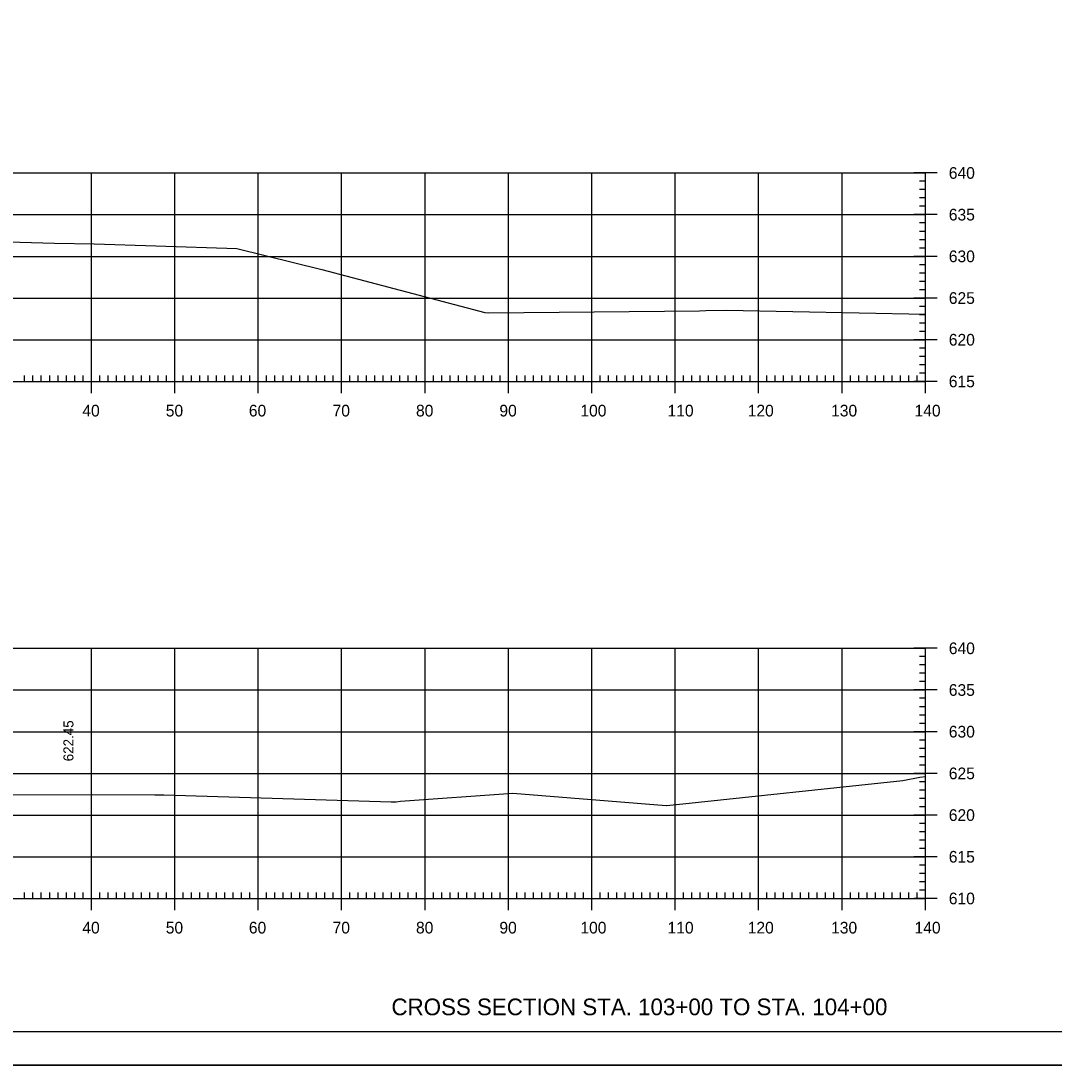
# Model space of a CAD drawing. Extents: x 1381471 to 1382703, y 370300 to 371487.
# Drawn here: x 1382168.2 to 1382292, y 370847.1 to 370972.4 of the extents above; entities that cross this region are included whole.
import ezdxf

# ---------------------------------------------------------------- set-up
doc = ezdxf.new("R2010")
doc.units = 0
doc.layers.add('Level 45', color=7, linetype='Continuous')

msp = doc.modelspace()

# ---------------------------------------------------------------- linework, layer by layer
at = {"layer": 'Level 45'}
for p, q in [((1381996.61, 370954.12), (1382276.61, 370954.12)), ((1382176.61, 370929.12), (1382176.61, 370954.12)), ((1382186.61, 370929.12), (1382186.61, 370954.12)), ((1382196.61, 370929.12), (1382196.61, 370954.12)), ((1382206.61, 370929.12), (1382206.61, 370954.12)), ((1382216.61, 370929.12), (1382216.61, 370954.12)), ((1382226.61, 370929.12), (1382226.61, 370954.12)), ((1382236.61, 370929.12), (1382236.61, 370954.12)), ((1382246.61, 370929.12), (1382246.61, 370954.12)), ((1382256.61, 370929.12), (1382256.61, 370954.12)), ((1382266.61, 370929.12), (1382266.61, 370954.12)), ((1382278.01, 370954.12), (1382275.21, 370954.12)), ((1382276.61, 370929.12), (1382276.61, 370954.12)), ((1382276.61, 370929.12), (1382276.61, 370954.12)), ((1382276.61, 370953.12), (1382275.91, 370953.12)), ((1382276.61, 370952.12), (1382275.91, 370952.12)), ((1382276.61, 370951.12), (1382275.91, 370951.12)), ((1382276.61, 370950.12), (1382275.91, 370950.12)), ((1381996.61, 370949.12), (1382276.61, 370949.12)), ((1382278.01, 370949.12), (1382275.21, 370949.12)), ((1382276.61, 370948.12), (1382275.91, 370948.12)), ((1382276.61, 370947.12), (1382275.91, 370947.12)), ((1382276.61, 370946.12), (1382275.91, 370946.12)), ((1382276.61, 370945.12), (1382275.91, 370945.12)), ((1381996.61, 370944.12), (1382276.61, 370944.12)), ((1382278.01, 370944.12), (1382275.21, 370944.12)), ((1382276.61, 370943.12), (1382275.91, 370943.12)), ((1382276.61, 370942.12), (1382275.91, 370942.12)), ((1382276.61, 370941.12), (1382275.91, 370941.12)), ((1382276.61, 370940.12), (1382275.91, 370940.12)), ((1381996.61, 370939.12), (1382276.61, 370939.12)), ((1382278.01, 370939.12), (1382275.21, 370939.12)), ((1382276.61, 370938.12), (1382275.91, 370938.12)), ((1382276.61, 370937.12), (1382275.91, 370937.12)), ((1382276.61, 370936.12), (1382275.91, 370936.12)), ((1382276.61, 370935.12), (1382275.91, 370935.12)), ((1381996.61, 370934.12), (1382276.61, 370934.12)), ((1382278.01, 370934.12), (1382275.21, 370934.12)), ((1382276.61, 370933.12), (1382275.91, 370933.12)), ((1382276.61, 370932.12), (1382275.91, 370932.12)), ((1382276.61, 370931.12), (1382275.91, 370931.12)), ((1382168.61, 370929.12), (1382168.61, 370929.82)), ((1382169.61, 370929.12), (1382169.61, 370929.82)), ((1382170.61, 370929.12), (1382170.61, 370929.82)), ((1382171.61, 370929.12), (1382171.61, 370929.82)), ((1382172.61, 370929.12), (1382172.61, 370929.82)), ((1382173.61, 370929.12), (1382173.61, 370929.82)), ((1382174.61, 370929.12), (1382174.61, 370929.82)), ((1382175.61, 370929.12), (1382175.61, 370929.82)), ((1382176.61, 370927.72), (1382176.61, 370930.52)), ((1382177.61, 370929.12), (1382177.61, 370929.82)), ((1382178.61, 370929.12), (1382178.61, 370929.82)), ((1382179.61, 370929.12), (1382179.61, 370929.82)), ((1382180.61, 370929.12), (1382180.61, 370929.82)), ((1382181.61, 370929.12), (1382181.61, 370929.82)), ((1382182.61, 370929.12), (1382182.61, 370929.82)), ((1382183.61, 370929.12), (1382183.61, 370929.82)), ((1382184.61, 370929.12), (1382184.61, 370929.82)), ((1382185.61, 370929.12), (1382185.61, 370929.82)), ((1382186.61, 370927.72), (1382186.61, 370930.52)), ((1382187.61, 370929.12), (1382187.61, 370929.82)), ((1382188.61, 370929.12), (1382188.61, 370929.82)), ((1382189.61, 370929.12), (1382189.61, 370929.82)), ((1382190.61, 370929.12), (1382190.61, 370929.82)), ((1382191.61, 370929.12), (1382191.61, 370929.82)), ((1382192.61, 370929.12), (1382192.61, 370929.82)), ((1382193.61, 370929.12), (1382193.61, 370929.82)), ((1382194.61, 370929.12), (1382194.61, 370929.82)), ((1382195.61, 370929.12), (1382195.61, 370929.82)), ((1382196.61, 370927.72), (1382196.61, 370930.52)), ((1382197.61, 370929.12), (1382197.61, 370929.82)), ((1382198.61, 370929.12), (1382198.61, 370929.82)), ((1382199.61, 370929.12), (1382199.61, 370929.82)), ((1382200.61, 370929.12), (1382200.61, 370929.82)), ((1382201.61, 370929.12), (1382201.61, 370929.82)), ((1382202.61, 370929.12), (1382202.61, 370929.82)), ((1382203.61, 370929.12), (1382203.61, 370929.82)), ((1382204.61, 370929.12), (1382204.61, 370929.82)), ((1382205.61, 370929.12), (1382205.61, 370929.82)), ((1382206.61, 370927.72), (1382206.61, 370930.52)), ((1382207.61, 370929.12), (1382207.61, 370929.82)), ((1382208.61, 370929.12), (1382208.61, 370929.82)), ((1382209.61, 370929.12), (1382209.61, 370929.82)), ((1382210.61, 370929.12), (1382210.61, 370929.82)), ((1382211.61, 370929.12), (1382211.61, 370929.82)), ((1382212.61, 370929.12), (1382212.61, 370929.82)), ((1382213.61, 370929.12), (1382213.61, 370929.82)), ((1382214.61, 370929.12), (1382214.61, 370929.82)), ((1382215.61, 370929.12), (1382215.61, 370929.82)), ((1382216.61, 370927.72), (1382216.61, 370930.52)), ((1382217.61, 370929.12), (1382217.61, 370929.82)), ((1382218.61, 370929.12), (1382218.61, 370929.82)), ((1382219.61, 370929.12), (1382219.61, 370929.82)), ((1382220.61, 370929.12), (1382220.61, 370929.82)), ((1382221.61, 370929.12), (1382221.61, 370929.82)), ((1382222.61, 370929.12), (1382222.61, 370929.82)), ((1382223.61, 370929.12), (1382223.61, 370929.82)), ((1382224.61, 370929.12), (1382224.61, 370929.82)), ((1382225.61, 370929.12), (1382225.61, 370929.82)), ((1382226.61, 370927.72), (1382226.61, 370930.52)), ((1382227.61, 370929.12), (1382227.61, 370929.82)), ((1382228.61, 370929.12), (1382228.61, 370929.82)), ((1382229.61, 370929.12), (1382229.61, 370929.82)), ((1382230.61, 370929.12), (1382230.61, 370929.82)), ((1382231.61, 370929.12), (1382231.61, 370929.82)), ((1382232.61, 370929.12), (1382232.61, 370929.82)), ((1382233.61, 370929.12), (1382233.61, 370929.82)), ((1382234.61, 370929.12), (1382234.61, 370929.82)), ((1382235.61, 370929.12), (1382235.61, 370929.82)), ((1382236.61, 370927.72), (1382236.61, 370930.52)), ((1382237.61, 370929.12), (1382237.61, 370929.82)), ((1382238.61, 370929.12), (1382238.61, 370929.82)), ((1382239.61, 370929.12), (1382239.61, 370929.82)), ((1382240.61, 370929.12), (1382240.61, 370929.82)), ((1382241.61, 370929.12), (1382241.61, 370929.82)), ((1382242.61, 370929.12), (1382242.61, 370929.82)), ((1382243.61, 370929.12), (1382243.61, 370929.82)), ((1382244.61, 370929.12), (1382244.61, 370929.82)), ((1382245.61, 370929.12), (1382245.61, 370929.82)), ((1382246.61, 370927.72), (1382246.61, 370930.52)), ((1382247.61, 370929.12), (1382247.61, 370929.82)), ((1382248.61, 370929.12), (1382248.61, 370929.82)), ((1382249.61, 370929.12), (1382249.61, 370929.82)), ((1382250.61, 370929.12), (1382250.61, 370929.82)), ((1382251.61, 370929.12), (1382251.61, 370929.82)), ((1382252.61, 370929.12), (1382252.61, 370929.82)), ((1382253.61, 370929.12), (1382253.61, 370929.82)), ((1382254.61, 370929.12), (1382254.61, 370929.82)), ((1382255.61, 370929.12), (1382255.61, 370929.82)), ((1382256.61, 370927.72), (1382256.61, 370930.52)), ((1382257.61, 370929.12), (1382257.61, 370929.82)), ((1382258.61, 370929.12), (1382258.61, 370929.82)), ((1382259.61, 370929.12), (1382259.61, 370929.82)), ((1382260.61, 370929.12), (1382260.61, 370929.82)), ((1382261.61, 370929.12), (1382261.61, 370929.82)), ((1382262.61, 370929.12), (1382262.61, 370929.82)), ((1382263.61, 370929.12), (1382263.61, 370929.82)), ((1382264.61, 370929.12), (1382264.61, 370929.82)), ((1382265.61, 370929.12), (1382265.61, 370929.82)), ((1382266.61, 370927.72), (1382266.61, 370930.52)), ((1382267.61, 370929.12), (1382267.61, 370929.82)), ((1382268.61, 370929.12), (1382268.61, 370929.82)), ((1382269.61, 370929.12), (1382269.61, 370929.82)), ((1382270.61, 370929.12), (1382270.61, 370929.82)), ((1382271.61, 370929.12), (1382271.61, 370929.82)), ((1382272.61, 370929.12), (1382272.61, 370929.82)), ((1382273.61, 370929.12), (1382273.61, 370929.82)), ((1382274.61, 370929.12), (1382274.61, 370929.82)), ((1382275.61, 370929.12), (1382275.61, 370929.82)), ((1382276.61, 370930.12), (1382275.91, 370930.12)), ((1382276.61, 370927.72), (1382276.61, 370930.52)), ((1381996.61, 370929.12), (1382276.61, 370929.12)), ((1381996.61, 370929.12), (1382276.61, 370929.12)), ((1382278.01, 370929.12), (1382275.21, 370929.12)), ((1381996.61, 370897.12), (1382276.61, 370897.12)), ((1382176.61, 370867.12), (1382176.61, 370897.12)), ((1382186.61, 370867.12), (1382186.61, 370897.12)), ((1382196.61, 370867.12), (1382196.61, 370897.12)), ((1382206.61, 370867.12), (1382206.61, 370897.12)), ((1382216.61, 370867.12), (1382216.61, 370897.12)), ((1382226.61, 370867.12), (1382226.61, 370897.12)), ((1382236.61, 370867.12), (1382236.61, 370897.12)), ((1382246.61, 370867.12), (1382246.61, 370897.12)), ((1382256.61, 370867.12), (1382256.61, 370897.12)), ((1382266.61, 370867.12), (1382266.61, 370897.12)), ((1382278.01, 370897.12), (1382275.21, 370897.12)), ((1382276.61, 370867.12), (1382276.61, 370897.12)), ((1382276.61, 370867.12), (1382276.61, 370897.12)), ((1382276.61, 370896.12), (1382275.91, 370896.12)), ((1382276.61, 370895.12), (1382275.91, 370895.12)), ((1382276.61, 370894.12), (1382275.91, 370894.12)), ((1381996.61, 370892.12), (1382276.61, 370892.12)), ((1382278.01, 370892.12), (1382275.21, 370892.12)), ((1382276.61, 370893.12), (1382275.91, 370893.12)), ((1382276.61, 370891.12), (1382275.91, 370891.12)), ((1382276.61, 370890.12), (1382275.91, 370890.12)), ((1382276.61, 370889.12), (1382275.91, 370889.12)), ((1381996.61, 370887.12), (1382276.61, 370887.12)), ((1382278.01, 370887.12), (1382275.21, 370887.12)), ((1382276.61, 370888.12), (1382275.91, 370888.12)), ((1382276.61, 370886.12), (1382275.91, 370886.12)), ((1382276.61, 370885.12), (1382275.91, 370885.12)), ((1382276.61, 370884.12), (1382275.91, 370884.12)), ((1381996.61, 370882.12), (1382276.61, 370882.12)), ((1382278.01, 370882.12), (1382275.21, 370882.12)), ((1382276.61, 370883.12), (1382275.91, 370883.12)), ((1382276.61, 370881.12), (1382275.91, 370881.12)), ((1382276.61, 370880.12), (1382275.91, 370880.12)), ((1382276.61, 370879.12), (1382275.91, 370879.12)), ((1381996.61, 370877.12), (1382276.61, 370877.12)), ((1382278.01, 370877.12), (1382275.21, 370877.12)), ((1382276.61, 370878.12), (1382275.91, 370878.12)), ((1382276.61, 370876.12), (1382275.91, 370876.12)), ((1382276.61, 370875.12), (1382275.91, 370875.12)), ((1382276.61, 370874.12), (1382275.91, 370874.12)), ((1381996.61, 370872.12), (1382276.61, 370872.12)), ((1382278.01, 370872.12), (1382275.21, 370872.12)), ((1382276.61, 370873.12), (1382275.91, 370873.12)), ((1382276.61, 370871.12), (1382275.91, 370871.12)), ((1382276.61, 370870.12), (1382275.91, 370870.12)), ((1382176.61, 370865.72), (1382176.61, 370868.52)), ((1382186.61, 370865.72), (1382186.61, 370868.52)), ((1382196.61, 370865.72), (1382196.61, 370868.52)), ((1382206.61, 370865.72), (1382206.61, 370868.52)), ((1382216.61, 370865.72), (1382216.61, 370868.52)), ((1382226.61, 370865.72), (1382226.61, 370868.52)), ((1382236.61, 370865.72), (1382236.61, 370868.52)), ((1382246.61, 370865.72), (1382246.61, 370868.52)), ((1382256.61, 370865.72), (1382256.61, 370868.52)), ((1382266.61, 370865.72), (1382266.61, 370868.52)), ((1382276.61, 370869.12), (1382275.91, 370869.12)), ((1382276.61, 370865.72), (1382276.61, 370868.52)), ((1381996.61, 370867.12), (1382276.61, 370867.12)), ((1381996.61, 370867.12), (1382276.61, 370867.12)), ((1382168.61, 370867.12), (1382168.61, 370867.82)), ((1382169.61, 370867.12), (1382169.61, 370867.82)), ((1382170.61, 370867.12), (1382170.61, 370867.82)), ((1382171.61, 370867.12), (1382171.61, 370867.82)), ((1382172.61, 370867.12), (1382172.61, 370867.82)), ((1382173.61, 370867.12), (1382173.61, 370867.82)), ((1382174.61, 370867.12), (1382174.61, 370867.82)), ((1382175.61, 370867.12), (1382175.61, 370867.82)), ((1382177.61, 370867.12), (1382177.61, 370867.82)), ((1382178.61, 370867.12), (1382178.61, 370867.82)), ((1382179.61, 370867.12), (1382179.61, 370867.82)), ((1382180.61, 370867.12), (1382180.61, 370867.82)), ((1382181.61, 370867.12), (1382181.61, 370867.82)), ((1382182.61, 370867.12), (1382182.61, 370867.82)), ((1382183.61, 370867.12), (1382183.61, 370867.82)), ((1382184.61, 370867.12), (1382184.61, 370867.82)), ((1382185.61, 370867.12), (1382185.61, 370867.82)), ((1382187.61, 370867.12), (1382187.61, 370867.82)), ((1382188.61, 370867.12), (1382188.61, 370867.82)), ((1382189.61, 370867.12), (1382189.61, 370867.82)), ((1382190.61, 370867.12), (1382190.61, 370867.82)), ((1382191.61, 370867.12), (1382191.61, 370867.82)), ((1382192.61, 370867.12), (1382192.61, 370867.82)), ((1382193.61, 370867.12), (1382193.61, 370867.82)), ((1382194.61, 370867.12), (1382194.61, 370867.82)), ((1382195.61, 370867.12), (1382195.61, 370867.82)), ((1382197.61, 370867.12), (1382197.61, 370867.82)), ((1382198.61, 370867.12), (1382198.61, 370867.82)), ((1382199.61, 370867.12), (1382199.61, 370867.82)), ((1382200.61, 370867.12), (1382200.61, 370867.82)), ((1382201.61, 370867.12), (1382201.61, 370867.82)), ((1382202.61, 370867.12), (1382202.61, 370867.82)), ((1382203.61, 370867.12), (1382203.61, 370867.82)), ((1382204.61, 370867.12), (1382204.61, 370867.82)), ((1382205.61, 370867.12), (1382205.61, 370867.82)), ((1382207.61, 370867.12), (1382207.61, 370867.82)), ((1382208.61, 370867.12), (1382208.61, 370867.82)), ((1382209.61, 370867.12), (1382209.61, 370867.82)), ((1382210.61, 370867.12), (1382210.61, 370867.82)), ((1382211.61, 370867.12), (1382211.61, 370867.82)), ((1382212.61, 370867.12), (1382212.61, 370867.82)), ((1382213.61, 370867.12), (1382213.61, 370867.82)), ((1382214.61, 370867.12), (1382214.61, 370867.82)), ((1382215.61, 370867.12), (1382215.61, 370867.82)), ((1382217.61, 370867.12), (1382217.61, 370867.82)), ((1382218.61, 370867.12), (1382218.61, 370867.82)), ((1382219.61, 370867.12), (1382219.61, 370867.82)), ((1382220.61, 370867.12), (1382220.61, 370867.82)), ((1382221.61, 370867.12), (1382221.61, 370867.82)), ((1382222.61, 370867.12), (1382222.61, 370867.82)), ((1382223.61, 370867.12), (1382223.61, 370867.82)), ((1382224.61, 370867.12), (1382224.61, 370867.82)), ((1382225.61, 370867.12), (1382225.61, 370867.82)), ((1382227.61, 370867.12), (1382227.61, 370867.82)), ((1382228.61, 370867.12), (1382228.61, 370867.82)), ((1382229.61, 370867.12), (1382229.61, 370867.82)), ((1382230.61, 370867.12), (1382230.61, 370867.82)), ((1382231.61, 370867.12), (1382231.61, 370867.82)), ((1382232.61, 370867.12), (1382232.61, 370867.82)), ((1382233.61, 370867.12), (1382233.61, 370867.82)), ((1382234.61, 370867.12), (1382234.61, 370867.82)), ((1382235.61, 370867.12), (1382235.61, 370867.82)), ((1382237.61, 370867.12), (1382237.61, 370867.82)), ((1382238.61, 370867.12), (1382238.61, 370867.82)), ((1382239.61, 370867.12), (1382239.61, 370867.82)), ((1382240.61, 370867.12), (1382240.61, 370867.82)), ((1382241.61, 370867.12), (1382241.61, 370867.82)), ((1382242.61, 370867.12), (1382242.61, 370867.82)), ((1382243.61, 370867.12), (1382243.61, 370867.82)), ((1382244.61, 370867.12), (1382244.61, 370867.82)), ((1382245.61, 370867.12), (1382245.61, 370867.82)), ((1382247.61, 370867.12), (1382247.61, 370867.82)), ((1382248.61, 370867.12), (1382248.61, 370867.82)), ((1382249.61, 370867.12), (1382249.61, 370867.82)), ((1382250.61, 370867.12), (1382250.61, 370867.82)), ((1382251.61, 370867.12), (1382251.61, 370867.82)), ((1382252.61, 370867.12), (1382252.61, 370867.82)), ((1382253.61, 370867.12), (1382253.61, 370867.82)), ((1382254.61, 370867.12), (1382254.61, 370867.82)), ((1382255.61, 370867.12), (1382255.61, 370867.82)), ((1382257.61, 370867.12), (1382257.61, 370867.82)), ((1382258.61, 370867.12), (1382258.61, 370867.82)), ((1382259.61, 370867.12), (1382259.61, 370867.82)), ((1382260.61, 370867.12), (1382260.61, 370867.82)), ((1382261.61, 370867.12), (1382261.61, 370867.82)), ((1382262.61, 370867.12), (1382262.61, 370867.82)), ((1382263.61, 370867.12), (1382263.61, 370867.82)), ((1382264.61, 370867.12), (1382264.61, 370867.82)), ((1382265.61, 370867.12), (1382265.61, 370867.82)), ((1382267.61, 370867.12), (1382267.61, 370867.82)), ((1382268.61, 370867.12), (1382268.61, 370867.82)), ((1382269.61, 370867.12), (1382269.61, 370867.82)), ((1382270.61, 370867.12), (1382270.61, 370867.82)), ((1382271.61, 370867.12), (1382271.61, 370867.82)), ((1382272.61, 370867.12), (1382272.61, 370867.82)), ((1382273.61, 370867.12), (1382273.61, 370867.82)), ((1382274.61, 370867.12), (1382274.61, 370867.82)), ((1382278.01, 370867.12), (1382275.21, 370867.12)), ((1382275.61, 370867.12), (1382275.61, 370867.82)), ((1382276.61, 370868.12), (1382275.91, 370868.12)), ((1382294.79, 370851.12), (1381978.61, 370851.12)), ((1381966.21, 370847.14), (1382299.55, 370847.14))]:
    msp.add_line(p, q, dxfattribs=at)
for points in [[(1381966.21, 371060.47), (1382299.55, 371060.47), (1382299.55, 370847.14), (1381966.21, 370847.14)], [(1382212.53, 371056.58), (1382232.15, 371056.58), (1382232.15, 371046.7), (1382248.27, 371046.7), (1382271.46, 371046.7), (1382271.46, 371022.37), (1382294.79, 371022.37), (1382294.79, 370851.12), (1381978.61, 370851.12), (1381978.61, 371056.58)]]:
    msp.add_lwpolyline(points, close=True, dxfattribs=at)
for points in [[(1382162.42, 370945.99), (1382172.18, 370945.72), (1382176.94, 370945.61), (1382184.33, 370945.37), (1382194.04, 370945.06), (1382204.23, 370942.53), (1382223.79, 370937.38), (1382224.26, 370937.34), (1382249.52, 370937.59), (1382250.29, 370937.63), (1382252.76, 370937.66), (1382276.61, 370937.2)], [(1382158.96, 370879.58), (1382184.22, 370879.56), (1382185.3, 370879.56), (1382212.56, 370878.7), (1382213.15, 370878.69), (1382213.68, 370878.77), (1382227.14, 370879.74), (1382245.51, 370878.27), (1382245.56, 370878.27), (1382246.75, 370878.39), (1382273.89, 370881.28), (1382275.95, 370881.66), (1382276.61, 370881.73)]]:
    msp.add_lwpolyline(points, dxfattribs=at)

# ---------------------------------------------------------------- texts
for s, height, p in [('640', 1.4, (1382279.41, 370953.42)), ('635', 1.4, (1382279.41, 370948.42)), ('630', 1.4, (1382279.41, 370943.42)), ('625', 1.4, (1382279.41, 370938.42)), ('620', 1.4, (1382279.41, 370933.42)), ('615', 1.4, (1382279.41, 370928.42)), ('40', 1.4, (1382175.53, 370924.92)), ('50', 1.4, (1382185.53, 370924.92)), ('60', 1.4, (1382195.49, 370924.92)), ('70', 1.4, (1382205.53, 370924.92)), ('80', 1.4, (1382215.53, 370924.92)), ('90', 1.4, (1382225.53, 370924.92)), ('100', 1.4, (1382235.24, 370924.92)), ('110', 1.4, (1382245.69, 370924.92)), ('120', 1.4, (1382255.3, 370924.92)), ('130', 1.4, (1382265.3, 370924.92)), ('140', 1.4, (1382275.3, 370924.92)), ('640', 1.4, (1382279.41, 370896.42)), ('635', 1.4, (1382279.41, 370891.42)), ('630', 1.4, (1382279.41, 370886.42)), ('625', 1.4, (1382279.41, 370881.42)), ('620', 1.4, (1382279.41, 370876.42)), ('615', 1.4, (1382279.41, 370871.42)), ('610', 1.4, (1382279.41, 370866.42)), ('40', 1.4, (1382175.53, 370862.92)), ('50', 1.4, (1382185.53, 370862.92)), ('60', 1.4, (1382195.49, 370862.92)), ('70', 1.4, (1382205.53, 370862.92)), ('80', 1.4, (1382215.53, 370862.92)), ('90', 1.4, (1382225.53, 370862.92)), ('100', 1.4, (1382235.24, 370862.92)), ('110', 1.4, (1382245.69, 370862.92)), ('120', 1.4, (1382255.3, 370862.92)), ('130', 1.4, (1382265.3, 370862.92)), ('140', 1.4, (1382275.3, 370862.92)), ('CROSS SECTION STA. 103+00 TO STA. 104+00', 2, (1382212.59, 370853.12))]:
    msp.add_text(s, height=height, dxfattribs=at).set_placement(p)
msp.add_text('622.45', height=1.2, rotation=90, dxfattribs=at).set_placement((1382174.46, 370883.57))

doc.saveas('drawing.dxf')
